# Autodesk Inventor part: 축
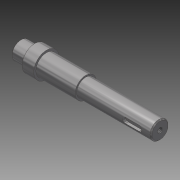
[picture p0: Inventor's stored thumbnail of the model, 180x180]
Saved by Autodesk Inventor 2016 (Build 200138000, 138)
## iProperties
Created: 2015-09
Part Number: 축
Material: 강철, 연강
Document SubType Name: Modeling
Designer: mduedu
Density: 7.86 g/cm^3
Mass: 263.424 g
Surface Area: 86.4309 cm^2
Volume: 33.5145 cm^3
Appearance: 반광택
Author: mduedu
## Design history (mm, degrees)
sketch "스케치1"
  geometry: L1 (-66.5, 0)-(66.5, 0); L2 (-66.5, 0)-(-66.5, 8.5); L3 (-66.5, 8.5)-(-51.5, 8.5); L4 (-51.5, 8.5)-(-51.5, 12); L5 (-51.5, 12)-(-40.5, 12); L6 (-40.5, 12)-(-40.5, 10); L7 (-40.5, 10)-(-3.5, 10); L8 (-3.5, 10)-(-3.5, 8.5); L9 (-3.5, 8.5)-(66.5, 8.5); L10 (66.5, 8.5)-(66.5, 0); 2 further points
  constraints: 20 end point, 5 parallel, 2 horizontal, 2 perpendicular, 1 coincident, 1 midpoint, 1 vertical
  dimensions: "d0" = 133 distance of L1.start L1.end; "d2" = 11 distance of L4.end L5.end; "d3" = 37 distance of L6.end L7.end; "d4" = 70 distance of L8.end L9.end; "d5" = 17 diameter of L3 L1; "d6" = 17 diameter of L9 L1; "d7" = 20 diameter of L7 L1; "d8" = 24 diameter of L5 L1
revolve "회전1" sketch "스케치1" stored, may be unused: angle "d9" = 90 deg
node "작업 평면1"
sketch "스케치2"
  geometry: L1 (10.5, 2.5)-(23.5, 2.5); L2 (23.5, -2.5)-(10.5, -2.5); L3 (10.5, 2.5)-(23.5, -2.5); L4 (23.5, 2.5)-(10.5, -2.5); L5 (35, -8.5)-(35, 8.5) reference; A1 r 2.5 centre (10.5, 0) between (10.5, 2.5) and (10.5, -2.5); A2 r 2.5 centre (23.5, 0) between (23.5, -2.5) and (23.5, 2.5); 2 further points
  constraints: 8 end point, 4 point on circle, 4 tangent, 2 centre point, 2 midpoint, 1 horizontal, 1 horizontal alignment, 1 parallel
  dimensions: "d10" = 18 dimension on A2 A1; "d12" = 9 distance edge to line of A2 L5; "d13" = 5 distance between parallel lines of L2 L1
extrude "돌출1" cut sketch "스케치2" distance "d14" = 3; taper "d15" = 0 deg
node "작업 평면2"
sketch "스케치4"
  geometry: L1 (9.5, -3)-(-6.5, -3); L2 (-6.5, 3)-(9.5, 3); L3 (-18.5, 10)-(-18.5, -10) reference; A1 r 3 centre (-6.5, 0) between (-6.5, 3) and (-6.5, -3); A2 r 3 centre (9.5, 0) between (9.5, -3) and (9.5, 3); 1 further point
  constraints: 4 end point, 4 point on circle, 4 tangent, 2 centre point, 1 horizontal, 1 horizontal alignment, 1 parallel
  dimensions: "d16" = 22 dimension on A1 A2; "d18" = 6 distance between parallel lines of L2 L1; "d19" = 9 distance edge to line of A1 L3
extrude "돌출2" cut sketch "스케치4" distance "d20" = 3.5; taper "d21" = 0 deg
sketch "스케치5"
  geometry: L1 (-3.5, 8.5)-(66.5, 8.5) reference; L2 (-3.5, -8.5)-(66.5, -8.5) reference; L3 (40.5, 8.5)-(40.5, -8.5); L4 (40.5, -6.5)-(38.5, -8.5); L5 (40.5, -8.5)-(38.5, -8.5); L6 (40.5, -8.5)-(40.5, -6.5); L7 (-3.5, -10)-(-3.5, 10) reference; 1 further point
  constraints: 8 end point, 4 point on line, 1 collinear, 1 perpendicular
  dimensions: "d22" = 4 diameter of L4.end L3; "d24" = 45 deg angle of L3 L4; "d26" = 44 distance between parallel lines of L3 L7
revolve "회전2" sketch "스케치5" stored, may be unused: angle "d27" = 90 deg
chamfer "모따기1" distance "d28" = 1; stored, may be unused: second distance "d29" = 2, angle "d30" = 45 deg
sketch "스케치6"
  geometry: L1 (40.5, -6.5)-(38.5, -8.5) reference; L2 (40.5, -6.5)-(42.5, -8.5) reference; 2 further points
  constraints: 1 coincident
hole "구멍1" diameter "d33" = 4.917; stored, may be unused: countersink angle "d37" = 90 deg, drill point angle "d39" = 118 deg; dims "d34" = 12, "d35" = 4, "d36" = 2, "d38" = 15, "d42" = 10, "d43" = 10
node "솔리드1"
